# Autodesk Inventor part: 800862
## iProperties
Created: 2007-11
Part Number: 800862
Document SubType Name: Modeling
Designer: TH
Density: 1.425 g/cm^3
Mass: 0.523521 g
Surface Area: 7.18024 cm^2
Volume: 0.367383 cm^3
Material: Acetal Resin, Black
Description: WIRE CONNECTING TUBE
Component Category: Fasteners
Author: TH
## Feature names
1. Extrusion1
